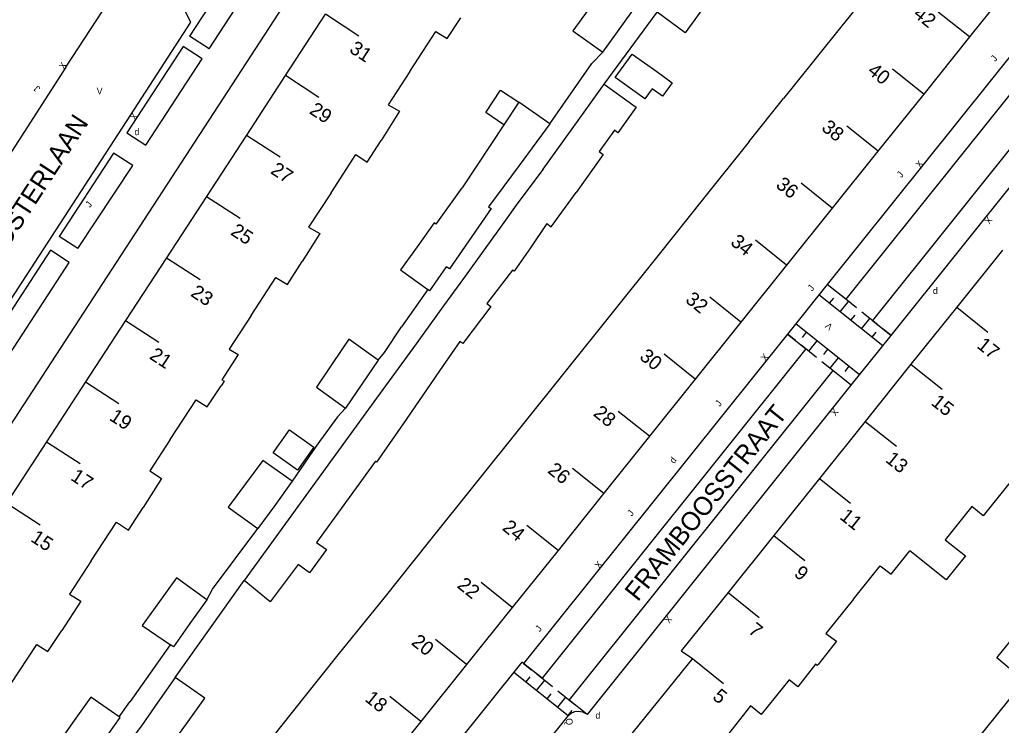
# Model space of a CAD drawing. Extents: x 134999 to 136502, y 457398 to 459002.
# Drawn here: x 135299.1 to 135372.9, y 457841.7 to 457894.8 of the extents above; entities that cross this region are included whole.
import ezdxf

# ---------------------------------------------------------------- set-up
doc = ezdxf.new("R2010")
doc.units = 0
for name, color, linetype in [('RI_DGTB_15', 7, 'Continuous'), ('RI_DGTB_29', 7, 'Continuous'), ('RI_DGTB_30', 7, 'Continuous'), ('RI_DGTB_31', 7, 'Continuous'), ('RI_DGTB_35', 7, 'Continuous'), ('RI_DGTB_36', 7, 'Continuous'), ('RI_DGTB_37', 7, 'Continuous'), ('RI_DGTB_4', 7, 'Continuous'), ('RI_DGTB_5', 7, 'Continuous'), ('RI_DGTB_53', 7, 'Continuous'), ('RI_DGTB_54', 7, 'Continuous'), ('RI_DGTB_6', 7, 'Continuous')]:
    doc.layers.add(name, color=color, linetype=linetype)

msp = doc.modelspace()

# ---------------------------------------------------------------- linework, layer by layer
at = {"layer": 'RI_DGTB_15'}
for p, q in [((135322.089, 457895.214), (135324.602, 457893.576)), ((135370.54, 457893.479), (135368.199, 457895.355)), ((135367.101, 457889.186), (135364.76, 457891.062)), ((135319.08, 457890.6), (135321.593, 457888.962)), ((135363.662, 457884.893), (135361.321, 457886.769)), ((135316.162, 457886.092), (135318.675, 457884.454)), ((135360.223, 457880.6), (135357.882, 457882.476)), ((135313.153, 457881.478), (135315.666, 457879.84)), ((135356.784, 457876.307), (135354.443, 457878.183)), ((135310.144, 457876.864), (135312.657, 457875.226)), ((135353.345, 457872.014), (135351.004, 457873.89)), ((135369.586, 457873.136), (135371.927, 457871.26)), ((135307.044, 457872.144), (135309.557, 457870.506)), ((135349.906, 457867.721), (135347.565, 457869.597)), ((135366.145, 457868.844), (135368.486, 457866.968)), ((135304.035, 457867.53), (135306.548, 457865.892)), ((135346.467, 457863.428), (135344.126, 457865.304)), ((135362.704, 457864.552), (135365.045, 457862.676)), ((135301.117, 457863.022), (135303.63, 457861.384)), ((135343.028, 457859.135), (135340.687, 457861.011)), ((135359.263, 457860.26), (135361.604, 457858.384)), ((135298.108, 457858.408), (135300.621, 457856.77)), ((135339.589, 457854.842), (135337.248, 457856.718)), ((135355.822, 457855.968), (135358.163, 457854.092)), ((135336.15, 457850.549), (135333.809, 457852.425)), ((135352.381, 457851.676), (135354.722, 457849.8)), ((135332.711, 457846.256), (135330.37, 457848.132)), ((135349.697, 457846.698), (135352.038, 457844.822)), ((135329.272, 457841.963), (135326.931, 457843.839))]:
    msp.add_line(p, q, dxfattribs=at)
at = {"layer": 'RI_DGTB_31'}
for p, q in [((135360.444, 457874.383), (135359.844, 457874.863)), ((135364.02, 457870.239), (135359.219, 457874.082)), ((135362.044, 457873.102), (135360.844, 457874.062)), ((135360.019, 457873.442), (135360.332, 457873.832)), ((135360.819, 457872.801), (135361.444, 457873.582)), ((135361.619, 457872.161), (135361.932, 457872.551)), ((135363.644, 457871.82), (135362.444, 457872.781)), ((135362.27, 457868.053), (135357.469, 457871.897)), ((135362.419, 457871.52), (135363.044, 457872.301)), ((135357.444, 457870.636), (135356.844, 457871.116)), ((135358.269, 457871.256), (135357.957, 457870.866)), ((135363.22, 457870.88), (135363.532, 457871.27)), ((135364.645, 457871.02), (135364.045, 457871.5)), ((135359.044, 457869.355), (135357.844, 457870.315)), ((135359.069, 457870.616), (135358.444, 457869.835)), ((135359.869, 457869.975), (135359.557, 457869.585)), ((135360.644, 457868.073), (135359.444, 457869.034)), ((135360.669, 457869.334), (135360.044, 457868.554)), ((135361.469, 457868.694), (135361.157, 457868.304)), ((135337.003, 457846.331), (135337.596, 457845.856)), ((135336.26, 457845.686), (135340.35, 457842.412)), ((135337.189, 457844.942), (135337.492, 457845.32)), ((135337.992, 457845.54), (135339.179, 457844.59)), ((135337.98, 457844.309), (135338.585, 457845.065)), ((135338.771, 457843.675), (135339.074, 457844.053)), ((135339.563, 457843.042), (135340.168, 457843.798)), ((135339.574, 457844.273), (135340.761, 457843.323)), ((135341.157, 457843.007), (135341.75, 457842.532)), ((135340.354, 457842.409), (135340.656, 457842.787))]:
    msp.add_line(p, q, dxfattribs=at)
msp.add_lwpolyline([(135361.646, 457867.272), (135361.045, 457867.753)], dxfattribs=at)
at = {"layer": 'RI_DGTB_4'}
for p, q in [((135373.979, 457897.772), (135370.54, 457893.479)), ((135319.097, 457890.589), (135322.103, 457895.205)), ((135370.54, 457893.479), (135367.1, 457889.186)), ((135316.166, 457886.089), (135319.097, 457890.589)), ((135367.1, 457889.186), (135363.661, 457884.893)), ((135313.155, 457881.476), (135316.166, 457886.089)), ((135363.661, 457884.893), (135360.222, 457880.601)), ((135310.148, 457876.862), (135313.155, 457881.476)), ((135360.222, 457880.601), (135356.783, 457876.308)), ((135373.026, 457877.429), (135369.585, 457873.137)), ((135307.063, 457872.131), (135310.148, 457876.862)), ((135356.783, 457876.308), (135353.344, 457872.015)), ((135369.585, 457873.137), (135366.144, 457868.845)), ((135304.054, 457867.516), (135307.063, 457872.131)), ((135353.344, 457872.015), (135349.905, 457867.722)), ((135366.144, 457868.845), (135362.704, 457864.552)), ((135301.121, 457863.02), (135304.054, 457867.516)), ((135349.905, 457867.722), (135346.466, 457863.429)), ((135362.704, 457864.552), (135359.263, 457860.26)), ((135298.112, 457858.405), (135301.121, 457863.02)), ((135346.466, 457863.429), (135343.027, 457859.136)), ((135359.263, 457860.26), (135355.822, 457855.968)), ((135343.027, 457859.136), (135339.588, 457854.843)), ((135355.822, 457855.968), (135352.381, 457851.676)), ((135339.588, 457854.843), (135336.149, 457850.55)), ((135336.149, 457850.55), (135332.71, 457846.257)), ((135332.71, 457846.257), (135329.271, 457841.964)), ((135354.061, 457843.14), (135349.485, 457837.321)), ((135329.271, 457841.964), (135325.832, 457837.671))]:
    msp.add_line(p, q, dxfattribs=at)
for points in [[(135352.381, 457851.676), (135348.861, 457847.285), (135349.697, 457846.698)], [(135349.697, 457846.698), (135344.809, 457840.663), (135349.233, 457837.181)]]:
    msp.add_lwpolyline(points, dxfattribs=at)
at = {"layer": 'RI_DGTB_5'}
for p, q in [((135364.242, 457898.439), (135360.846, 457894.198)), ((135360.846, 457894.198), (135357.392, 457889.884)), ((135357.392, 457889.884), (135356.562, 457888.845)), ((135353.972, 457885.61), (135350.534, 457881.316)), ((135350.534, 457881.316), (135347.096, 457877.021)), ((135347.096, 457877.021), (135343.658, 457872.728)), ((135343.658, 457872.728), (135340.221, 457868.434)), ((135340.221, 457868.434), (135336.783, 457864.14)), ((135336.783, 457864.14), (135333.345, 457859.846)), ((135333.345, 457859.846), (135329.907, 457855.552)), ((135319.594, 457842.67), (135316.157, 457838.376))]:
    msp.add_line(p, q, dxfattribs=at)
for points in [[(135328.448, 457890.877), (135330.404, 457893.881), (135331.255, 457893.354), (135332.289, 457894.923)], [(135328.448, 457890.877), (135326.822, 457888.38), (135327.673, 457887.899), (135326.271, 457885.696)], [(135353.972, 457885.61), (135356.562, 457888.845)], [(135322.512, 457881.761), (135324.382, 457884.633), (135325.236, 457884.068), (135326.271, 457885.696)], [(135322.512, 457881.761), (135320.815, 457879.155), (135321.681, 457878.686), (135320.339, 457876.577)], [(135316.501, 457872.529), (135318.354, 457875.375), (135319.242, 457874.853), (135320.339, 457876.577)], [(135316.501, 457872.529), (135314.85, 457869.994), (135315.531, 457869.581), (135314.295, 457867.689), (135314.473, 457867.576), (135314.245, 457867.233)], [(135310.413, 457863.18), (135312.36, 457866.172), (135313.186, 457865.645), (135314.245, 457867.233)], [(135310.413, 457863.18), (135308.88, 457860.826), (135309.759, 457860.248), (135308.37, 457858.076)], [(135374.609, 457862.307), (135375.138, 457861.89), (135371.585, 457857.442), (135370.709, 457858.141)], [(135304.476, 457854.065), (135306.369, 457856.972), (135307.278, 457856.369), (135308.37, 457858.076)], [(135370.709, 457858.141), (135368.717, 457855.648), (135370.237, 457854.434), (135368.791, 457852.624), (135366.055, 457854.817)], [(135329.907, 457855.552), (135326.475, 457851.253)], [(135361.813, 457851.167), (135363.821, 457853.679), (135364.641, 457853.048), (135366.055, 457854.817)], [(135304.476, 457854.065), (135302.83, 457851.536), (135303.692, 457851.022), (135302.258, 457848.823)], [(135326.475, 457851.253), (135323.019, 457846.973)], [(135361.813, 457851.167), (135359.748, 457848.584), (135360.549, 457848.007), (135359.154, 457846.248)], [(135298.404, 457844.737), (135300.374, 457847.762), (135301.216, 457847.226), (135302.258, 457848.823)], [(135323.019, 457846.973), (135319.594, 457842.67)], [(135359.154, 457846.248), (135359.095, 457846.174), (135358.965, 457846.289), (135357.641, 457844.581), (135356.966, 457845.102), (135354.874, 457842.486), (135354.061, 457843.14)]]:
    msp.add_lwpolyline(points, dxfattribs=at)
at = {"layer": 'RI_DGTB_53'}
for p, q in [((135318.05, 457903.034), (135311.871, 457893.533)), ((135313.331, 457892.583), (135311.871, 457893.533)), ((135311.375, 457892.771), (135307.147, 457886.27)), ((135312.827, 457891.826), (135311.375, 457892.771)), ((135302.557, 457891.207), (135290.664, 457872.707)), ((135306.139, 457884.746), (135302.063, 457878.463)), ((135303.472, 457877.549), (135302.063, 457878.463)), ((135301.394, 457877.431), (135294.992, 457867.562)), ((135302.81, 457876.513), (135301.394, 457877.431))]:
    msp.add_line(p, q, dxfattribs=at)
for points in [[(135391.703, 457911.803), (135361.237, 457873.747)], [(135393.679, 457910.17), (135363.251, 457872.135)], [(135313.331, 457892.583), (135319.521, 457902.064), (135318.05, 457903.034)], [(135302.557, 457891.207), (135307.169, 457898.272)], [(135291.044, 457863.468), (135291.745, 457863.472), (135295.535, 457869.31), (135307.437, 457887.63), (135311.966, 457894.593), (135311.544, 457895.418)], [(135307.147, 457886.27), (135308.58, 457885.334), (135312.827, 457891.826)], [(135303.472, 457877.549), (135307.598, 457883.81), (135306.139, 457884.746)], [(135294.992, 457867.562), (135296.373, 457866.634), (135302.81, 457876.513)], [(135361.237, 457873.747), (135359.844, 457874.863)], [(135363.251, 457872.135), (135364.645, 457871.02)], [(135356.844, 457871.116), (135358.238, 457870)], [(135358.238, 457870), (135338.397, 457845.216)], [(135360.253, 457868.386), (135340.42, 457843.596)], [(135361.646, 457867.272), (135360.253, 457868.386)], [(135338.397, 457845.216), (135337.003, 457846.331)], [(135340.42, 457843.596), (135341.75, 457842.532)]]:
    msp.add_lwpolyline(points, dxfattribs=at)
at = {"layer": 'RI_DGTB_54'}
for p, q in [((135390.304, 457912.912), (135359.844, 457874.863)), ((135364.645, 457871.02), (135390.995, 457903.957)), ((135343.062, 457889.927), (135347.041, 457895.352)), ((135342.13, 457891.479), (135342.969, 457892.338)), ((135338.963, 457886.938), (135342.13, 457891.479)), ((135359.844, 457874.863), (135356.844, 457871.116)), ((135329.797, 457874.474), (135327.806, 457871.667)), ((135356.844, 457871.116), (135337.003, 457846.331)), ((135361.646, 457867.272), (135364.645, 457871.02)), ((135323.002, 457864.891), (135323.599, 457865.54)), ((135313.591, 457851.911), (135317.009, 457856.498)), ((135310.797, 457845.283), (135315.976, 457852.581)), ((135313.16, 457851.129), (135313.591, 457851.911)), ((135336.864, 457846.442), (135331.249, 457839.417)), ((135337.003, 457846.331), (135336.864, 457846.442)), ((135370.583, 457839.961), (135374.666, 457845.018))]:
    msp.add_line(p, q, dxfattribs=at)
for points in [[(135352.269, 457941.458), (135349.721, 457943.116), (135342.096, 457931.491), (135336.126, 457922.35), (135322.387, 457901.187), (135294.106, 457857.745), (135282.083, 457839.389), (135271.452, 457823.013), (135274.006, 457821.437)], [(135326.069, 457869.158), (135326.536, 457869.744), (135327.806, 457871.667)], [(135341.75, 457842.532), (135341.814, 457842.481), (135361.646, 457867.272)], [(135323.002, 457864.891), (135321.439, 457862.76), (135319.599, 457860.047)], [(135306.581, 457842.313), (135307.382, 457843.454), (135307.42, 457843.468), (135310.43, 457847.727)], [(135340.35, 457842.412), (135332.006, 457831.983), (135332.608, 457826.658)], [(135340.35, 457842.412), (135340.578, 457842.593), (135340.847, 457842.705), (135341.136, 457842.74), (135341.423, 457842.695), (135341.688, 457842.574), (135341.75, 457842.532)]]:
    msp.add_lwpolyline(points, dxfattribs=at)
at = {"layer": 'RI_DGTB_6'}
for p, q in [((135343.062, 457889.927), (135345.216, 457888.379)), ((135346.125, 457888.836), (135345.742, 457889.11)), ((135338.48, 457883.529), (135340.523, 457886.394)), ((135338.48, 457883.529), (135336.574, 457880.997)), ((135330.432, 457879.392), (135332.37, 457882.121))]:
    msp.add_line(p, q, dxfattribs=at)
for points in [[(135344.06, 457893.863), (135347.268, 457898.35)], [(135341.857, 457895.521), (135340.694, 457893.955), (135342.969, 457892.338)], [(135350.417, 457895.517), (135349.16, 457893.78), (135347.041, 457895.352)], [(135342.969, 457892.338), (135344.06, 457893.863)], [(135345.742, 457889.11), (135343.893, 457890.431), (135345.157, 457892.199), (135347.013, 457890.873)], [(135347.013, 457890.873), (135348.188, 457890.033), (135347.46, 457889.015), (135346.661, 457889.586), (135346.125, 457888.836)], [(135335.524, 457886.872), (135334.148, 457887.785), (135335.273, 457889.48), (135336.649, 457888.566)], [(135341.679, 457888.003), (135343.062, 457889.927)], [(135336.649, 457888.566), (135335.524, 457886.872)], [(135338.963, 457886.938), (135336.649, 457888.566)], [(135340.523, 457886.394), (135341.679, 457888.003)], [(135345.216, 457888.379), (135345.465, 457888.2), (135344.083, 457886.276), (135343.831, 457886.457)], [(135335.524, 457886.872), (135334.536, 457885.384)], [(135338.963, 457886.938), (135336.665, 457883.818)], [(135343.831, 457886.457), (135342.678, 457884.857)], [(135334.536, 457885.384), (135332.37, 457882.121)], [(135342.678, 457884.857), (135342.989, 457884.635), (135340.946, 457881.77)], [(135336.665, 457883.818), (135334.366, 457880.696)], [(135338.748, 457879.438), (135339.079, 457879.201), (135340.946, 457881.77)], [(135334.366, 457880.696), (135334.549, 457880.566), (135331.426, 457876.021), (135331.177, 457876.192)], [(135336.574, 457880.997), (135335.377, 457879.336)], [(135330.432, 457879.392), (135330.279, 457879.499), (135328.989, 457877.695)], [(135335.377, 457879.336), (135332.277, 457875.035)], [(135338.748, 457879.438), (135337.507, 457877.624)], [(135328.989, 457877.695), (135327.743, 457875.954), (135329.797, 457874.474)], [(135337.507, 457877.624), (135336.297, 457875.855), (135336.169, 457875.938), (135334.235, 457873.426)], [(135331.177, 457876.192), (135329.93, 457874.378), (135329.797, 457874.474)], [(135332.277, 457875.035), (135330.985, 457873.243)], [(135330.985, 457873.243), (135328.919, 457870.398)], [(135334.235, 457873.426), (135334.538, 457873.198), (135332.431, 457870.401), (135332.193, 457870.572)], [(135326.069, 457869.158), (135323.85, 457870.741), (135322.591, 457868.88)], [(135328.919, 457870.398), (135325.734, 457866.013)], [(135332.193, 457870.572), (135330.954, 457868.763)], [(135322.591, 457868.88), (135321.411, 457867.136), (135323.599, 457865.54)], [(135326.069, 457869.158), (135324.834, 457867.349)], [(135330.954, 457868.763), (135327.887, 457864.284)], [(135324.834, 457867.349), (135323.599, 457865.54)], [(135325.734, 457866.013), (135322.472, 457861.523)], [(135319.997, 457860.882), (135318.165, 457862.174), (135319.388, 457863.909), (135321.221, 457862.618), (135319.997, 457860.882)], [(135327.887, 457864.284), (135327.716, 457864.034), (135325.941, 457861.491), (135325.851, 457861.559), (135324.593, 457859.819)], [(135319.599, 457860.047), (135317.391, 457861.607), (135316.088, 457859.846)], [(135322.472, 457861.523), (135319.287, 457857.139)], [(135319.599, 457860.047), (135318.272, 457858.229)], [(135316.088, 457859.846), (135314.784, 457858.085), (135317.009, 457856.498)], [(135324.593, 457859.819), (135321.424, 457855.435)], [(135318.272, 457858.229), (135317.009, 457856.498)], [(135319.287, 457857.139), (135315.976, 457852.581)], [(135321.424, 457855.435), (135322.161, 457854.911), (135320.881, 457853.161), (135320.041, 457853.791), (135317.923, 457850.974)], [(135313.16, 457851.129), (135310.883, 457852.784), (135309.594, 457850.99)], [(135317.923, 457850.974), (135315.976, 457852.581)], [(135313.16, 457851.129), (135311.894, 457849.338)], [(135309.594, 457850.99), (135308.305, 457849.197), (135310.43, 457847.727)], [(135311.894, 457849.338), (135310.648, 457847.576), (135310.43, 457847.727)], [(135374.666, 457845.018), (135372.604, 457846.762), (135373.999, 457848.499)], [(135310.797, 457845.283), (135309.486, 457843.414)], [(135311.629, 457841.796), (135313.006, 457843.715), (135310.797, 457845.283)], [(135306.581, 457842.313), (135304.449, 457843.792), (135303.189, 457842.03)], [(135309.486, 457843.414), (135308.244, 457841.645), (135306.11, 457838.819), (135308.275, 457837.119), (135308.305, 457837.161)], [(135305.371, 457840.469), (135306.656, 457842.261), (135306.581, 457842.313)], [(135303.189, 457842.03), (135301.929, 457840.268), (135304.049, 457838.626)], [(135308.305, 457837.161), (135311.629, 457841.796)]]:
    msp.add_lwpolyline(points, dxfattribs=at)

# ---------------------------------------------------------------- texts
at = {"layer": 'RI_DGTB_29'}
for height, p in [(0.5, (135307.723, 457886.091)), (0.499, (135367.794, 457874.133)), (0.5, (135342.405, 457842.177))]:
    msp.add_text('d', height=height, dxfattribs=at).set_placement(p)
msp.add_text('d', height=0.499, rotation=51.32444, dxfattribs=at).set_placement((135348.311, 457861.33))
at = {"layer": 'RI_DGTB_30'}
for s, height, rotation, p in [('X', 0.5, 57.09271, (135302.421, 457890.997)), ('X', 0.5, 236.98814, (135307.573, 457887.84)), ('X', 0.499, 51.32444, (135366.828, 457883.587)), ('X', 0.499, 231.33052, (135371.907, 457880.011)), ('V', 0.5, 141.34533, (135360.302, 457871.755)), ('X', 0.499, 51.32444, (135355.188, 457869.047)), ('X', 0.499, 231.33052, (135360.337, 457865.576)), ('X', 0.499, 51.32444, (135342.686, 457853.43)), ('X', 0.499, 231.33052, (135347.827, 457849.968))]:
    msp.add_text(s, height=height, rotation=rotation, dxfattribs=at).set_placement(p)
msp.add_text('V', height=0.5, dxfattribs=at).set_placement((135304.877, 457889.159))
at = {"layer": 'RI_DGTB_31'}
for s, height, rotation, p in [('J', 0.499, 51.32444, (135372.48, 457891.593)), ('J', 0.499, 139.59823, (135300.678, 457889.655)), ('J', 0.499, 51.32444, (135365.416, 457882.848)), ('J', 0.499, 51.32444, (135304.368, 457880.599)), ('J', 0.499, 51.32444, (135358.703, 457874.31)), ('J', 0.499, 51.32444, (135351.748, 457865.627)), ('J', 0.499, 51.32444, (135345.138, 457857.373)), ('J', 0.499, 51.32444, (135338.214, 457848.67)), ('Q', 0.5, 276.80579, (135340.159, 457842.179))]:
    msp.add_text(s, height=height, rotation=rotation, dxfattribs=at).set_placement(p)
at = {"layer": 'RI_DGTB_35'}
msp.add_text('5', height=1.054, rotation=321.2772, dxfattribs=at).set_placement((135351.147, 457843.707))
at = {"layer": 'RI_DGTB_36'}
for s, rotation, p in [('42', 321.3006, (135366.259, 457895.079)), ('31', 326.8907, (135323.821, 457892.381)), ('40', 321.3006, (135362.807, 457890.797)), ('29', 326.8907, (135320.812, 457887.768)), ('38', 321.3006, (135359.34, 457886.525)), ('27', 326.8907, (135317.894, 457883.26)), ('36', 321.3006, (135355.908, 457882.226)), ('25', 326.8907, (135314.885, 457878.646)), ('34', 321.3006, (135352.496, 457877.913)), ('23', 326.8907, (135311.877, 457874.031)), ('32', 321.3006, (135349.103, 457873.583)), ('17', 321.2772, (135371.035, 457870.145)), ('21', 326.8907, (135308.777, 457869.312)), ('30', 321.3006, (135345.651, 457869.3)), ('15', 321.2772, (135367.594, 457865.854)), ('19', 326.8907, (135305.767, 457864.698)), ('28', 321.3006, (135342.173, 457865.039)), ('13', 321.2772, (135364.153, 457861.562)), ('26', 321.3006, (135338.74, 457860.741)), ('17', 326.8907, (135302.85, 457860.189)), ('11', 321.2772, (135360.712, 457857.269)), ('24', 321.3006, (135335.328, 457856.426)), ('15', 326.8907, (135299.842, 457855.575)), ('9', 321.2772, (135357.271, 457852.978)), ('22', 321.3006, (135331.933, 457852.097)), ('7', 321.2772, (135353.83, 457848.686)), ('20', 321.3006, (135328.483, 457847.814)), ('18', 321.3006, (135324.991, 457843.563))]:
    msp.add_text(s, height=1.054, rotation=rotation, dxfattribs=at).set_placement(p)
at = {"layer": 'RI_DGTB_37'}
for s, rotation, p in [('KLOOSTERLAAN', 56.96442, (135296.094, 457874.39)), ('FRAMBOOSSTRAAT', 51.3407, (135345.59, 457850.93))]:
    msp.add_text(s, height=1.4, rotation=rotation, dxfattribs=at).set_placement(p)

doc.saveas('drawing.dxf')
